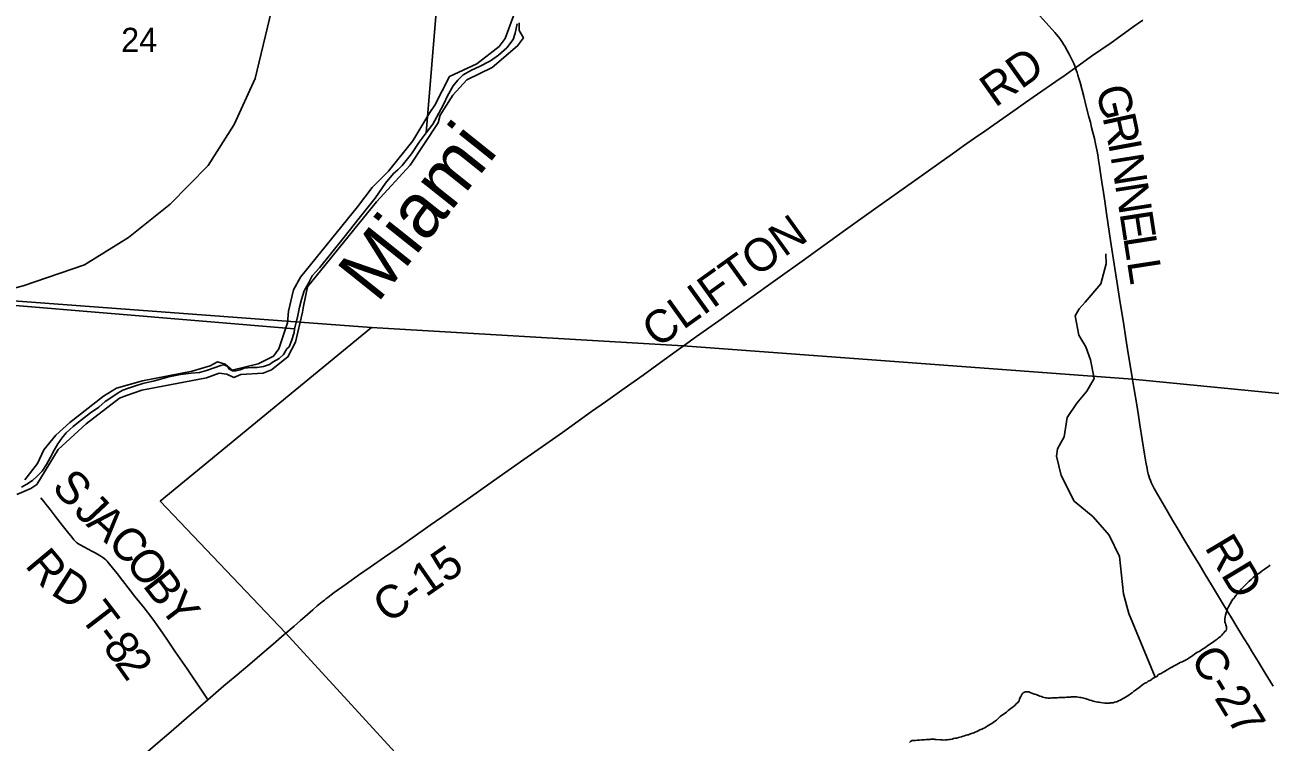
# Model space of a CAD drawing. Extents: x -1.4 to 35.4, y 0 to 22.
# Drawn here: x 19.08 to 21.235, y 14.137 to 15.379 of the extents above; entities that cross this region are included whole.
import ezdxf

# ---------------------------------------------------------------- set-up
doc = ezdxf.new("R2010")
doc.units = 0
for name, color, linetype in [('GM_X_County_Road', 7, 'Continuous'), ('GM_X_County_Road_Text', 7, 'Continuous'), ('GM_X_Major_River', 7, 'Continuous'), ('GM_X_Major_River_Text', 7, 'Continuous'), ('GM_X_Minor_River', 7, 'Continuous'), ('GM_X_Rail_Line', 7, 'Continuous'), ('GM_X_Section', 7, 'Continuous'), ('GM_X_Section_Text', 7, 'Continuous'), ('GM_X_Township_Road', 7, 'Continuous'), ('GM_X_Township_Road_Text', 7, 'Continuous'), ('SC_Scratch1', 7, 'Continuous')]:
    doc.layers.add(name, color=color, linetype=linetype)

msp = doc.modelspace()

# ---------------------------------------------------------------- linework, layer by layer
at = {"layer": 'GM_X_County_Road'}
for points in [[(20.8979, 15.3045), (20.8972, 15.3064), (20.8949, 15.3118), (20.8917, 15.3189), (20.8894, 15.3237), (20.8871, 15.3282), (20.8845, 15.3333), (20.8821, 15.3376), (20.8799, 15.3414), (20.878, 15.3445), (20.8756, 15.3482), (20.8733, 15.3517), (20.8707, 15.3553), (20.8681, 15.3587), (20.8654, 15.362), (20.8623, 15.3658), (20.8524, 15.3769), (20.8255, 15.4064)], [(20.8979, 15.3045), (20.926, 15.3245), (20.9596, 15.3481), (20.989, 15.3689), (20.9981, 15.3753), (21.0148, 15.3869)], [(20.2194, 14.8226), (20.2424, 14.8392), (20.2809, 14.8666), (20.3283, 14.9007), (20.383, 14.9396), (20.4254, 14.97), (20.5004, 15.0242), (20.5525, 15.0614), (20.6178, 15.1078), (20.6618, 15.1392), (20.6855, 15.1559), (20.7044, 15.1693), (20.7232, 15.1825), (20.741, 15.195), (20.7721, 15.2168), (20.7953, 15.2329), (20.8115, 15.2443), (20.8323, 15.2588), (20.8639, 15.2807), (20.8801, 15.292), (20.8953, 15.3027), (20.8979, 15.3045)], [(20.9967, 14.765), (20.9926, 14.7899), (20.9893, 14.8102), (20.9853, 14.836), (20.981, 14.8636), (20.9755, 14.8977), (20.9695, 14.9355), (20.966, 14.957), (20.9585, 15.0059), (20.9562, 15.0213), (20.9518, 15.0521), (20.9487, 15.0736), (20.9464, 15.0889), (20.9437, 15.1067), (20.9415, 15.1221), (20.9396, 15.1345), (20.938, 15.1449), (20.9365, 15.1542), (20.935, 15.1625), (20.9328, 15.173), (20.9307, 15.182), (20.9281, 15.1925), (20.9259, 15.2013), (20.9238, 15.2102), (20.9213, 15.2199), (20.9168, 15.2376), (20.9123, 15.2551), (20.9059, 15.2794), (20.904, 15.2862), (20.9023, 15.292), (20.9008, 15.2965), (20.8994, 15.3006), (20.8979, 15.3045)], [(19.5316, 14.3258), (19.546, 14.3382), (19.5569, 14.3476), (19.5691, 14.3583), (19.5783, 14.3663), (19.5863, 14.3731), (19.5946, 14.38), (19.5986, 14.3833), (19.6012, 14.3855), (19.6044, 14.3879), (19.6104, 14.3924), (19.6155, 14.3962), (19.6347, 14.4098), (19.6451, 14.4173), (19.6576, 14.4261), (19.6777, 14.44), (19.7028, 14.4575), (19.7262, 14.4739), (19.7516, 14.4917), (19.7816, 14.5127), (19.8015, 14.5266), (19.8381, 14.5522), (19.8514, 14.5615), (19.9011, 14.5967), (19.9437, 14.6267), (19.9814, 14.6531), (20.0103, 14.6735), (20.0609, 14.7096), (20.0848, 14.7264), (20.113, 14.7467), (20.1501, 14.7728), (20.1799, 14.7942), (20.2074, 14.814), (20.2194, 14.8226)], [(21.2398, 14.2344), (21.226, 14.2567), (21.2139, 14.2769), (21.2028, 14.2951), (21.1971, 14.3046), (21.1901, 14.3161), (21.1789, 14.3342), (21.1661, 14.3555), (21.1606, 14.3645), (21.1507, 14.381), (21.1332, 14.4097), (21.1225, 14.4273), (21.1118, 14.4451), (21.1024, 14.4608), (21.0952, 14.4727), (21.0854, 14.4889), (21.0755, 14.5054), (21.0657, 14.5218), (21.0564, 14.5376), (21.0444, 14.5583), (21.0362, 14.5724), (21.0342, 14.5762), (21.0324, 14.5796), (21.0306, 14.5833), (21.0291, 14.5867), (21.0277, 14.5902), (21.0263, 14.5942), (21.025, 14.598), (21.024, 14.6017), (21.0229, 14.6062), (21.0219, 14.6108), (21.0199, 14.622), (21.0176, 14.6356), (21.0096, 14.6864), (21.0069, 14.7026), (21.0034, 14.7246), (20.9996, 14.7477), (20.9967, 14.765)], [(19.3968, 14.2106), (19.4247, 14.2346), (19.4441, 14.251), (19.4698, 14.2723), (19.4949, 14.2941), (19.5096, 14.3069), (19.5287, 14.3234), (19.5316, 14.3258)], [(19.285, 14.1142), (19.3064, 14.1326), (19.3333, 14.1559), (19.3644, 14.1828), (19.38, 14.1961), (19.3968, 14.2106)]]:
    msp.add_lwpolyline(points, dxfattribs=at)
at = {"layer": 'GM_X_Major_River'}
for points in [[(19.9259, 15.3943), (19.9111, 15.3556), (19.9009, 15.3414), (19.8624, 15.3116), (19.8149, 15.2895), (19.7896, 15.2397), (19.7809, 15.2274), (19.7518, 15.178), (19.7093, 15.1256), (19.6811, 15.0974), (19.6557, 15.0639), (19.5571, 14.9422), (19.5449, 14.9201), (19.5365, 14.8835), (19.5349, 14.8631), (19.5198, 14.818), (19.5105, 14.8057), (19.4837, 14.7919), (19.4391, 14.7812), (19.4269, 14.7917), (19.4137, 14.7954), (19.4007, 14.7885), (19.3698, 14.7797), (19.2836, 14.7628), (19.239, 14.7498), (19.2163, 14.7359), (19.1578, 14.6906), (19.1338, 14.6684), (19.1131, 14.6431), (19.102, 14.6195), (19.0802, 14.5916)], [(19.9355, 15.3823), (19.9356, 15.369), (19.9429, 15.3567), (19.9327, 15.3425), (19.8887, 15.3053), (19.8451, 15.2835), (19.8206, 15.2572), (19.8057, 15.2337), (19.7986, 15.2224), (19.7953, 15.2092), (19.7467, 15.1361), (19.6884, 15.0726), (19.5692, 14.9252), (19.5624, 14.8917), (19.5607, 14.8818), (19.5485, 14.8294), (19.5354, 14.804), (19.5069, 14.7819), (19.4924, 14.7758), (19.4541, 14.7736), (19.4419, 14.7682), (19.4295, 14.7742), (19.4163, 14.776), (19.3945, 14.7678), (19.2828, 14.7465), (19.2561, 14.7376), (19.2443, 14.7326), (19.1861, 14.6885), (19.1381, 14.6441), (19.1008, 14.5835), (19.0908, 14.5766), (19.0663, 14.5661)]]:
    msp.add_lwpolyline(points, dxfattribs=at)
at = {"layer": 'GM_X_Minor_River'}
for points in [[(21.0358, 14.2497), (20.9906, 14.3602), (20.9809, 14.3938), (20.9741, 14.4585), (20.9562, 14.4953), (20.9284, 14.527), (20.8955, 14.5546), (20.8731, 14.5987), (20.8654, 14.6323), (20.8671, 14.6448), (20.8782, 14.6658), (20.8837, 14.6991), (20.9001, 14.7243), (20.9179, 14.7448), (20.9301, 14.7669), (20.9242, 14.7993), (20.9159, 14.8215), (20.9041, 14.8415), (20.8972, 14.8751), (20.9046, 14.8875), (20.9147, 14.899), (20.9418, 14.9308), (20.9512, 14.9655), (20.9507, 14.9826)], [(21.0358, 14.2497), (21.0388, 14.2511), (21.0419, 14.2541), (21.0465, 14.2563), (21.0499, 14.2586), (21.053, 14.2601), (21.0553, 14.2619), (21.058, 14.263), (21.0614, 14.2653), (21.0633, 14.2664), (21.0656, 14.2678), (21.0687, 14.2693), (21.0721, 14.2712), (21.0763, 14.2734), (21.0794, 14.2749), (21.0828, 14.2763), (21.0859, 14.2782), (21.092, 14.2811), (21.0947, 14.283), (21.0977, 14.2852), (21.1008, 14.2871), (21.1042, 14.2893), (21.1081, 14.2927), (21.113, 14.2949), (21.1161, 14.2968), (21.1191, 14.2986), (21.1218, 14.3005), (21.1241, 14.3023), (21.1272, 14.3046), (21.1299, 14.3061), (21.1322, 14.3079), (21.1349, 14.3098), (21.1375, 14.3117), (21.1398, 14.3135), (21.1429, 14.3158), (21.1448, 14.3172), (21.1467, 14.3184), (21.149, 14.3202), (21.151, 14.3225), (21.1529, 14.3247), (21.1548, 14.3266), (21.1564, 14.3289), (21.159, 14.3307), (21.1594, 14.333), (21.1591, 14.3368), (21.1584, 14.3402), (21.1577, 14.3433), (21.1566, 14.3452), (21.1562, 14.3509), (21.1575, 14.357), (21.1591, 14.3626), (21.1602, 14.3653), (21.1606, 14.3676), (21.1618, 14.3694), (21.1626, 14.3717), (21.1684, 14.3819), (21.1703, 14.3845), (21.1723, 14.3864), (21.1738, 14.389), (21.1761, 14.3916), (21.1788, 14.3946), (21.1819, 14.3988), (21.1854, 14.4029), (21.1888, 14.4063), (21.1915, 14.4089), (21.1938, 14.4112), (21.1965, 14.4138), (21.1988, 14.416), (21.2019, 14.419), (21.2057, 14.422), (21.2096, 14.425), (21.2138, 14.428), (21.2176, 14.4309), (21.2211, 14.4336), (21.2245, 14.4362), (21.2283, 14.4388), (21.2318, 14.4414), (21.2349, 14.4436)], [(20.7715, 14.1847), (20.7764, 14.1877), (20.7784, 14.1891), (20.7818, 14.1921), (20.7883, 14.1974), (20.7902, 14.1981), (20.7929, 14.2007), (20.7956, 14.2033), (20.7983, 14.2056), (20.8006, 14.209), (20.8014, 14.2116), (20.8018, 14.2135), (20.8034, 14.2165), (20.8046, 14.2188), (20.8057, 14.2211), (20.8076, 14.2229), (20.8099, 14.224), (20.8118, 14.2244), (20.8149, 14.2243), (20.8172, 14.2243), (20.8198, 14.2231), (20.8236, 14.2216), (20.8274, 14.2204), (20.83, 14.2196), (20.8364, 14.2168), (20.8391, 14.216), (20.8413, 14.2152), (20.8436, 14.2148), (20.8459, 14.214), (20.8478, 14.214), (20.85, 14.2136), (20.8519, 14.2135), (20.8546, 14.2135), (20.8573, 14.2138), (20.8603, 14.2142), (20.863, 14.2141), (20.8652, 14.2141), (20.8671, 14.2141), (20.869, 14.2144), (20.8709, 14.2144), (20.8728, 14.2144), (20.8747, 14.2147), (20.8774, 14.2147), (20.8801, 14.2147), (20.8827, 14.215), (20.885, 14.215), (20.8869, 14.2153), (20.8892, 14.2153), (20.8911, 14.2156), (20.893, 14.2156), (20.896, 14.2156), (20.9002, 14.2155), (20.9028, 14.2151), (20.9055, 14.2147), (20.9078, 14.2143), (20.91, 14.2139), (20.9123, 14.2131), (20.9146, 14.2126), (20.9165, 14.2122), (20.9199, 14.2111), (20.9229, 14.2099), (20.9259, 14.2091), (20.9286, 14.2083), (20.9312, 14.2078), (20.9339, 14.207), (20.9365, 14.2066), (20.9388, 14.2062), (20.9414, 14.2058), (20.949, 14.2049), (20.9513, 14.2049), (20.954, 14.2049), (20.9566, 14.2048), (20.9589, 14.2052), (20.9616, 14.2051), (20.9635, 14.2055), (20.9657, 14.2062), (20.9677, 14.2069), (20.9696, 14.2073), (20.9715, 14.208), (20.9734, 14.2091), (20.9761, 14.2102), (20.9783, 14.2114), (20.9814, 14.2132), (20.9845, 14.2151), (20.9875, 14.2169), (20.9906, 14.2188), (20.9933, 14.221), (20.9959, 14.2229), (20.9986, 14.2247), (21.0017, 14.227), (21.0044, 14.2292), (21.0082, 14.2318), (21.0113, 14.2344), (21.0147, 14.237), (21.0182, 14.2393), (21.0212, 14.2407), (21.0239, 14.2426), (21.027, 14.2441), (21.0296, 14.2459), (21.0327, 14.2478), (21.0358, 14.2497)], [(20.6107, 14.1365), (20.613, 14.1387), (20.6156, 14.1402), (20.6187, 14.1401), (20.6213, 14.1401), (20.624, 14.1405), (20.6259, 14.1408), (20.6282, 14.1408), (20.6316, 14.1411), (20.6343, 14.1414), (20.6369, 14.1414), (20.6396, 14.1417), (20.6419, 14.1417), (20.6441, 14.1421), (20.646, 14.142), (20.6479, 14.1424), (20.6502, 14.1424), (20.6533, 14.1423), (20.6551, 14.1419), (20.657, 14.1419), (20.6646, 14.141), (20.6673, 14.141), (20.6699, 14.1409), (20.673, 14.1413), (20.676, 14.1412), (20.6787, 14.1416), (20.6813, 14.1419), (20.6848, 14.1426), (20.6871, 14.1433), (20.6901, 14.1441), (20.6928, 14.1444), (20.6954, 14.1451), (20.6977, 14.1458), (20.7008, 14.1466), (20.7038, 14.1477), (20.7061, 14.1484), (20.7091, 14.1491), (20.7111, 14.1498), (20.713, 14.1502), (20.7149, 14.1509), (20.7183, 14.152), (20.7202, 14.1527), (20.7221, 14.1535), (20.7244, 14.1546), (20.7271, 14.1557), (20.7297, 14.1568), (20.7324, 14.1587), (20.7359, 14.1597), (20.7385, 14.1608), (20.7412, 14.1623), (20.7435, 14.1638), (20.7454, 14.1649), (20.7481, 14.1668), (20.7512, 14.1683), (20.7534, 14.1697), (20.7557, 14.1712), (20.758, 14.1731), (20.7611, 14.1753), (20.7649, 14.1787), (20.768, 14.1817), (20.7715, 14.1847)]]:
    msp.add_lwpolyline(points, dxfattribs=at)
at = {"layer": 'GM_X_Rail_Line'}
msp.add_lwpolyline([(19.507, 15.4036), (19.4789, 15.286), (19.4423, 15.2064), (19.3975, 15.1352), (19.3315, 15.0687), (19.2598, 15.0109), (19.1832, 14.9638), (19.0775, 14.9272), (18.9881, 14.9042), (18.88, 14.8771), (18.7441, 14.8404), (18.641, 14.7966), (18.5197, 14.7379), (18.3965, 14.6703), (18.2988, 14.5997), (18.2068, 14.5258), (18.1293, 14.4427), (18.0673, 14.3607), (18.0142, 14.2768), (17.973, 14.1858), (17.9006, 14.0223), (17.7249, 13.6273), (17.4667, 13.0546)], dxfattribs=at)
at = {"layer": 'GM_X_Section'}
msp.add_lwpolyline([(18.8122, 15.8676), (19.823, 15.7773), (19.7747, 15.1918), (19.7627, 15.1761), (19.7495, 15.1559), (19.7333, 15.1357), (19.7254, 15.1282), (19.7183, 15.1215), (19.704, 15.1047), (19.6862, 15.0792), (19.6587, 15.0445), (19.6325, 15.0115), (19.59, 14.9585), (19.5776, 14.9446), (19.5702, 14.9304), (19.5636, 14.9187), (19.5588, 14.9037), (19.5552, 14.8905), (19.5522, 14.8727), (19.5466, 14.8527), (18.7324, 14.921)], close=True, dxfattribs=at)
for points in [[(19.9318, 15.3809), (19.9285, 15.3643), (19.9253, 15.3538), (19.9141, 15.3392), (19.8999, 15.3265), (19.8857, 15.3169), (19.867, 15.3066), (19.8529, 15.3004), (19.8384, 15.2927), (19.8292, 15.2833), (19.8214, 15.2736), (19.8117, 15.256), (19.805, 15.2425), (19.7964, 15.2263), (19.7863, 15.2072), (19.7747, 15.1918), (19.823, 15.7773)], [(18.7324, 14.921), (19.5466, 14.8527), (19.5465, 14.8463), (19.5418, 14.832), (19.5374, 14.8218), (19.5336, 14.8181), (19.5277, 14.8083), (19.5201, 14.8013), (19.5101, 14.7957), (19.5036, 14.7909), (19.4933, 14.7877), (19.4823, 14.786), (19.4721, 14.7857), (19.46, 14.7844), (19.4527, 14.7819), (19.4451, 14.7801), (19.4394, 14.7802), (19.4334, 14.7837), (19.4312, 14.7875), (19.4275, 14.7895), (19.4245, 14.7903), (19.4195, 14.7892), (19.4077, 14.7853), (19.3948, 14.7805), (19.3822, 14.7773), (19.3678, 14.7757), (19.3496, 14.7737), (19.3291, 14.7695), (19.3044, 14.763), (19.2842, 14.7581), (19.2697, 14.7537), (19.2579, 14.7494), (19.2499, 14.7465), (19.2415, 14.7417), (19.2323, 14.7354), (19.2193, 14.7269), (19.2082, 14.7169), (19.194, 14.7076), (19.1783, 14.6954), (19.1674, 14.6865), (19.1637, 14.6835), (19.1518, 14.6727), (19.1445, 14.6633), (19.1371, 14.6536), (19.1309, 14.6427), (19.1246, 14.6303), (19.1176, 14.6176), (19.1103, 14.6063), (19.1014, 14.5978), (19.0937, 14.5903), (19.0838, 14.584), (19.0746, 14.5789)]]:
    msp.add_lwpolyline(points, dxfattribs=at)
at = {"layer": 'GM_X_Township_Road'}
msp.add_lwpolyline([(19.108, 14.5604), (19.1133, 14.5536), (19.1165, 14.5495), (19.1195, 14.5458), (19.1241, 14.54), (19.1327, 14.5287), (19.145, 14.5128), (19.1539, 14.5014), (19.162, 14.4917), (19.1652, 14.4876), (19.1666, 14.4859), (19.1685, 14.4842), (19.1698, 14.483), (19.1715, 14.4816), (19.1737, 14.4801), (19.1762, 14.4787), (19.1835, 14.4746), (19.1962, 14.4681), (19.2008, 14.4656), (19.2059, 14.4628), (19.2089, 14.4611), (19.212, 14.459), (19.2149, 14.457), (19.2175, 14.455), (19.2201, 14.4526), (19.2224, 14.4503), (19.2243, 14.4482), (19.2265, 14.4456), (19.232, 14.4389), (19.2397, 14.4291), (19.2492, 14.4168), (19.2632, 14.399), (19.2707, 14.3896), (19.2866, 14.3697), (19.2999, 14.3525), (19.3048, 14.3461), (19.3088, 14.3406), (19.3146, 14.3325), (19.326, 14.3154), (19.3408, 14.2933), (19.3609, 14.2639), (19.3869, 14.2253), (19.3938, 14.2151), (19.3968, 14.2106)], dxfattribs=at)
at = {"layer": 'SC_Scratch1'}
for points in [[(17.0598, 13.0546), (20.6952, 13.0546), (20.6941, 13.0557), (20.0998, 13.7058), (19.5313, 14.3263), (19.3146, 14.5543), (19.6799, 14.855), (19.0057, 14.9053)], [(19.0057, 14.9053), (19.6799, 14.855), (20.2192, 14.8232), (20.9965, 14.7655), (22.1854, 14.6488)], [(22.1854, 14.6488), (20.9965, 14.7655), (20.2192, 14.8232), (19.6799, 14.855), (19.3146, 14.5543), (19.5313, 14.3263), (20.0998, 13.7058), (20.6941, 13.0557), (20.6952, 13.0546), (23.8598, 13.0546)]]:
    msp.add_lwpolyline(points, dxfattribs=at)

# ---------------------------------------------------------------- texts
at = {"layer": 'GM_X_County_Road_Text'}
for s, height, rotation, p in [('RD', 0.05682, 35.3103, (20.759, 15.2348)), ('G', 0.0568, 283.6131, (20.9328, 15.2677)), ('R', 0.0568, 282.2469, (20.9445, 15.2195)), ('I', 0.0568, 280.5353, (20.9543, 15.1743)), ('N', 0.0568, 279.0719, (20.9585, 15.1517)), ('N', 0.0568, 278.8287, (20.9664, 15.1024)), ('CLIFTON', 0.05682, 35.7064, (20.1747, 14.8181)), ('E', 0.0568, 278.8302, (20.9741, 15.053)), ('L', 0.0568, 278.8289, (20.9806, 15.011)), ('L', 0.0568, 278.828, (20.9871, 14.969)), ('C-15', 0.05682, 34.8255, (19.7084, 14.3414)), ('RD', 0.05682, 300.9641, (21.1204, 14.4745)), ('C-27', 0.05682, 301.3175, (21.0956, 14.2825))]:
    msp.add_text(s, height=height, rotation=rotation, dxfattribs=at).set_placement(p)
at = {"layer": 'GM_X_Major_River_Text'}
msp.add_text('Miami', height=0.09468, rotation=51.3964, dxfattribs=at).set_placement((19.69, 14.8956))
at = {"layer": 'GM_X_Section_Text'}
msp.add_text('24', height=0.04186, rotation=0, dxfattribs=at).set_placement((19.2469, 15.332))
at = {"layer": 'GM_X_Township_Road_Text'}
for s, rotation, p in [('S', 313.1517, (19.1249, 14.5769)), ('J', 313.1985, (19.1631, 14.5361)), ('A', 317.5471, (19.1847, 14.5134)), ('C', 313.9595, (19.221, 14.4803)), ('R', 309.7961, (19.079, 14.4426)), ('O', 307.522, (19.2523, 14.448)), ('D', 327.5144, (19.1229, 14.3943)), ('B', 307.4717, (19.2827, 14.4083)), ('Y', 307.4717, (19.3111, 14.3713)), ('T', 307.4965, (19.1737, 14.354)), ('-', 307.2102, (19.1996, 14.3204)), ('8', 306.5577, (19.2136, 14.3019)), ('2', 305.5552, (19.2343, 14.274))]:
    msp.add_text(s, height=0.0568, rotation=rotation, dxfattribs=at).set_placement(p)

doc.saveas('drawing.dxf')
